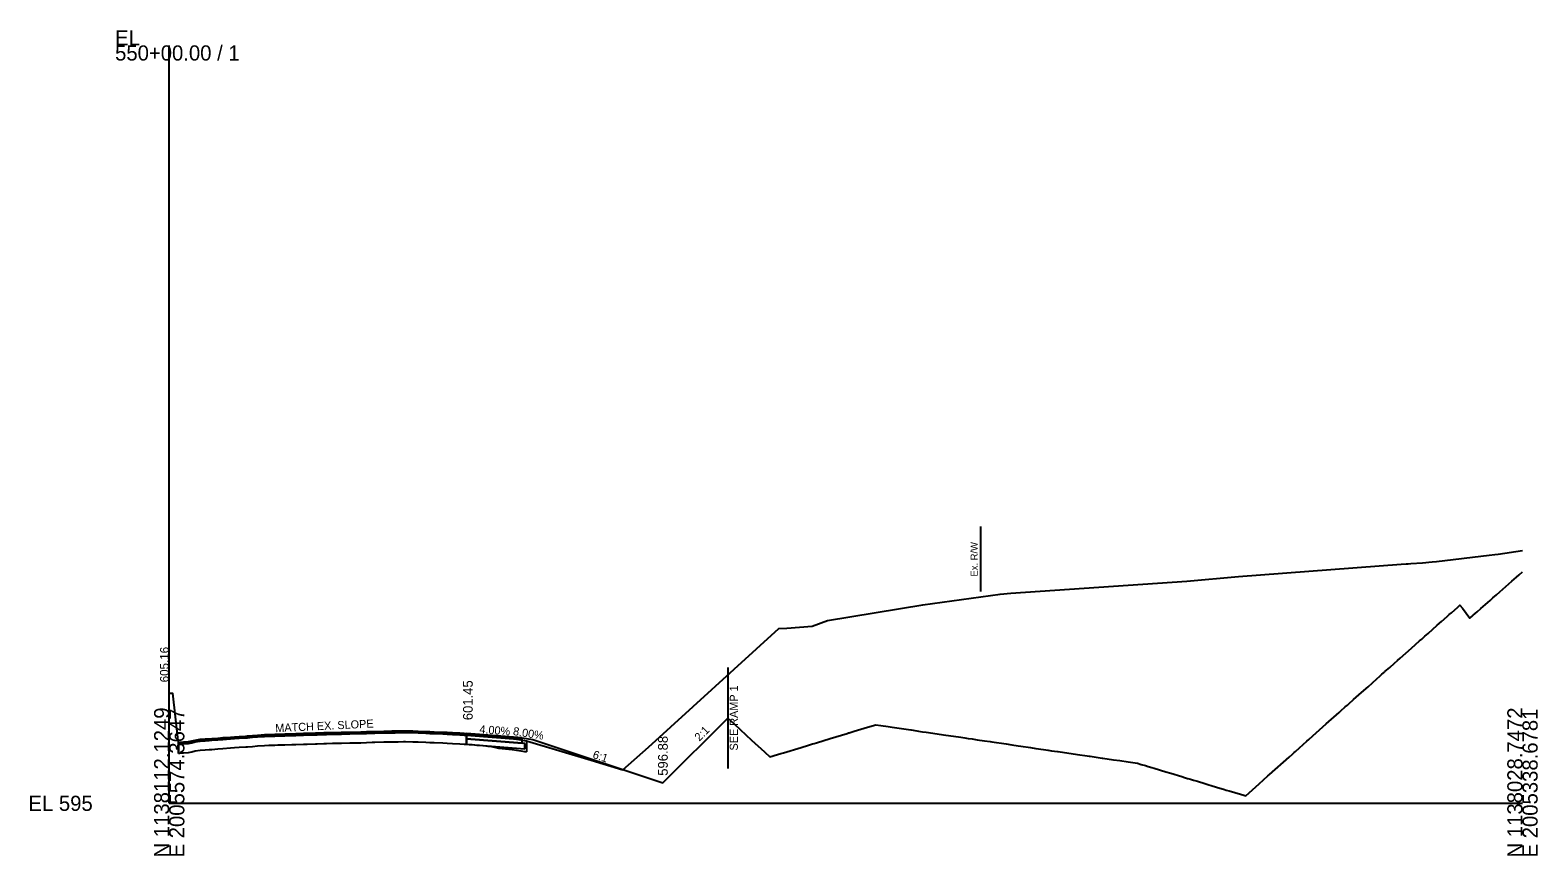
# Model space of a CAD drawing. Extents: x -201 to 2007062, y -213 to 1139737.
# Drawn here: x -25.7 to 252.8, y 5990.3 to 6142.7 of the extents above; entities that cross this region are included whole.
import ezdxf

# ---------------------------------------------------------------- set-up
doc = ezdxf.new("R2010")
doc.units = 0
for name, color, linetype in [('Default', 7, 'Continuous'), ('RD_DTM_Design_FG', 7, 'Continuous'), ('RD_GPK_XS_Cell', 7, 'Continuous'), ('RD_Sketch1', 7, 'Continuous'), ('RD_XS_Base', 7, 'Continuous'), ('RD_XS_EarthShd', 7, 'Continuous'), ('RD_XS_ExGround', 7, 'Continuous'), ('RD_XS_ExPaveRet', 7, 'Continuous'), ('RD_XS_ExRW', 7, 'Continuous'), ('RD_XS_PaveOvlay', 7, 'Continuous'), ('RD_XS_PaveShd', 7, 'Continuous'), ('RD_XS_SideStreet', 7, 'Continuous'), ('RD_XS_TieSlope', 7, 'Continuous'), ('RD_XS_TX_Ditch', 7, 'Continuous'), ('RD_XS_TX_Elev_EX', 7, 'Continuous'), ('RD_XS_TX_Elev_PR', 7, 'Continuous'), ('RD_XS_TX_Slope', 7, 'Continuous')]:
    doc.layers.add(name, color=color, linetype=linetype)

msp = doc.modelspace()

# ---------------------------------------------------------------- linework, layer by layer
at = {"layer": 'RD_DTM_Design_FG'}
msp.add_lwpolyline([(103.17, 6015.74), (104.42, 6014.59), (107.59, 6011.65), (109.95, 6009.48), (110.02, 6009.41), (110.94, 6008.56), (112.37, 6008.99), (112.99, 6009.18), (113.46, 6009.32), (116.74, 6010.32), (118.09, 6010.73), (118.84, 6010.96), (119.16, 6011.06), (119.6, 6011.19), (122.09, 6011.95), (125.26, 6012.91), (125.51, 6012.99), (125.59, 6013.01), (125.8, 6013.08), (126.51, 6013.29), (128.98, 6014.04), (130.52, 6014.51), (131.47, 6014.37), (132.83, 6014.17), (133.56, 6014.06), (136.99, 6013.55), (137.01, 6013.55), (137.08, 6013.54), (138.12, 6013.38), (138.41, 6013.34), (139.19, 6013.22), (139.86, 6013.12), (141.04, 6012.95), (141.45, 6012.89), (143.44, 6012.6), (143.97, 6012.52), (146.26, 6012.18), (147.01, 6012.07), (147.61, 6011.98), (148.31, 6011.88), (149.27, 6011.73), (150.64, 6011.53), (151.69, 6011.38), (151.99, 6011.33), (154.61, 6010.95), (155.67, 6010.79), (156.85, 6010.62), (157.32, 6010.55), (159.14, 6010.28), (160.12, 6010.14), (161.51, 6009.93), (161.97, 6009.86), (162.34, 6009.81), (162.37, 6009.8), (163.01, 6009.71), (164.11, 6009.55), (164.2, 6009.54), (167.82, 6009.01), (169.57, 6008.75), (169.92, 6008.7), (170.11, 6008.67), (171.26, 6008.5), (172.33, 6008.35), (172.5, 6008.32), (174.45, 6008.04), (175.63, 6007.87), (177.17, 6007.64), (178.87, 6007.39), (179.58, 6007.18), (180.35, 6006.95), (180.82, 6006.8), (181.54, 6006.59), (181.93, 6006.47), (184.14, 6005.81), (185.02, 6005.54), (187.06, 6004.93), (187.55, 6004.78), (188.14, 6004.6), (188.18, 6004.59), (188.68, 6004.44), (189.23, 6004.27), (189.95, 6004.06), (190.54, 6003.88), (190.74, 6003.82), (191.31, 6003.65), (192.07, 6003.42), (192.48, 6003.3), (193.49, 6002.99), (194.93, 6002.56), (195.29, 6002.45), (195.81, 6002.3), (197.89, 6001.68), (198.53, 6001.48), (198.89, 6001.38), (201.36, 6003.59), (202.97, 6005.04), (203.26, 6005.3), (206.87, 6008.52), (207.49, 6009.07), (207.76, 6009.31), (207.85, 6009.4), (208.04, 6009.57), (208.8, 6010.24), (210.18, 6011.47), (210.54, 6011.8), (211.27, 6012.45), (213.73, 6014.64), (214.7, 6015.5), (215.14, 6015.89), (216.14, 6016.79), (216.43, 6017.04), (217.27, 6017.8), (217.65, 6018.13), (217.91, 6018.36), (218.79, 6019.14), (220.26, 6020.45), (221.47, 6021.52), (223.09, 6022.96), (223.64, 6023.45), (224.04, 6023.81), (224.48, 6024.2), (224.6, 6024.3), (225.47, 6025.07), (226.33, 6025.84), (226.89, 6026.33), (227.39, 6026.77), (229.49, 6028.64), (230.99, 6029.96), (231.39, 6030.32), (231.95, 6030.82), (232.28, 6031.11), (232.55, 6031.35), (234.26, 6032.85), (235.06, 6033.56), (236.08, 6034.46), (236.48, 6034.82), (236.9, 6035.18), (238.03, 6036.18), (238.43, 6036.54), (238.9, 6036.01), (240.29, 6034.18), (240.34, 6034.22), (240.69, 6034.53), (240.9, 6034.72), (241.65, 6035.37), (242.3, 6035.94), (242.3, 6035.95), (244.01, 6037.45), (244.53, 6037.91), (245.19, 6038.49), (245.81, 6039.04), (246.36, 6039.52), (248.05, 6041.01), (248.92, 6041.76), (249.39, 6042.18), (250, 6042.72)], dxfattribs=at)
at = {"layer": 'RD_GPK_XS_Cell'}
for q in [(0, 6139.89), (250, 6000)]:
    msp.add_line((0, 6000), q, dxfattribs=at)
at = {"layer": 'RD_XS_Base'}
for points in [[(65.19, 6011.75), (54.94, 6012.56)], [(54.94, 6012.56), (54.94, 6011.9)], [(65.69, 6011.05), (65.19, 6011.09), (54.94, 6011.9)], [(54.94, 6011.9), (54.94, 6010.9)], [(54.94, 6011.9), (65.19, 6011.09)], [(54.94, 6010.9), (65.69, 6010.05)], [(65.19, 6011.09), (65.19, 6011.75)], [(65.69, 6010.05), (65.69, 6011.05)]]:
    msp.add_lwpolyline(points, dxfattribs=at)
at = {"layer": 'RD_XS_EarthShd'}
msp.add_lwpolyline([(65.19, 6012.08), (67.19, 6011.76)], dxfattribs=at)
at = {"layer": 'RD_XS_ExGround'}
msp.add_lwpolyline([(0, 6020.33), (0.63, 6020.35), (1.62, 6011.58), (1.7, 6011.21), (2.11, 6011.3), (2.64, 6011.32), (3.57, 6011.38), (4.18, 6011.51), (4.79, 6011.66), (5.69, 6011.81), (6.65, 6011.87), (7.4, 6011.91), (7.86, 6011.96), (8.95, 6012.05), (9.93, 6012.12), (11.35, 6012.23), (12.05, 6012.29), (12.92, 6012.36), (14.18, 6012.42), (14.49, 6012.45), (15.37, 6012.51), (16.3, 6012.58), (17.62, 6012.67), (18.42, 6012.71), (19.52, 6012.74), (20.09, 6012.77), (20.76, 6012.79), (21.36, 6012.81), (22.66, 6012.85), (23.37, 6012.87), (24.78, 6012.93), (25.46, 6012.94), (27.02, 6012.99), (27.36, 6013), (28.59, 6013.04), (29.03, 6013.05), (30.16, 6013.07), (31.49, 6013.09), (31.84, 6013.1), (33.36, 6013.16), (35.39, 6013.19), (36.43, 6013.24), (37.51, 6013.27), (37.99, 6013.28), (39.63, 6013.32), (41.13, 6013.35), (41.76, 6013.36), (42.3, 6013.37), (43.25, 6013.39), (43.66, 6013.4), (45, 6013.37), (46, 6013.33), (47.4, 6013.27), (48.12, 6013.24), (48.96, 6013.21), (50.53, 6013.14), (51.35, 6013.1), (52.36, 6013.05), (53.66, 6012.99), (54.48, 6012.94), (54.91, 6012.9), (55.42, 6012.88), (55.99, 6012.83), (56.8, 6012.75), (57.34, 6012.7), (58.52, 6012.59), (58.88, 6012.55), (59.51, 6012.47), (60.31, 6012.32), (60.85, 6012.19), (61.5, 6012.12), (63.34, 6011.94), (64.95, 6011.71), (65.61, 6011.59), (65.99, 6011.53), (77.92, 6007.96), (83.8, 6006.16), (88.52, 6010.34), (112.64, 6032.24), (114.11, 6032.35), (118.78, 6032.68), (121.59, 6033.71), (139.21, 6036.61), (153.51, 6038.57), (155.45, 6038.77), (188.01, 6040.99), (197.54, 6041.88), (227.56, 6044.12), (228.5, 6044.19), (228.91, 6044.22), (229.38, 6044.26), (231.5, 6044.41), (233.29, 6044.54), (234.12, 6044.6), (243.86, 6045.8), (244.92, 6045.93), (245.54, 6046), (250, 6046.63)], dxfattribs=at)
at = {"layer": 'RD_XS_ExPaveRet'}
for p, q in [((1.7, 6009.22), (1.7, 6011.22)), ((1.7, 6010.88), (1.7, 6009.22)), ((18.42, 6010.71), (19.52, 6010.74)), ((18.42, 6010.71), (19.52, 6010.74)), ((19.52, 6010.74), (20.09, 6010.77)), ((19.52, 6010.74), (20.09, 6010.77)), ((20.09, 6010.77), (20.76, 6010.79)), ((20.09, 6010.77), (20.76, 6010.79)), ((20.76, 6010.79), (21.36, 6010.81)), ((20.76, 6010.79), (21.36, 6010.81)), ((21.36, 6010.81), (22.66, 6010.85)), ((21.36, 6010.81), (22.66, 6010.85)), ((22.66, 6010.85), (23.37, 6010.87)), ((22.66, 6010.85), (23.37, 6010.87)), ((23.37, 6010.87), (24.78, 6010.93)), ((23.37, 6010.87), (24.78, 6010.93)), ((24.78, 6010.93), (25.46, 6010.94)), ((24.78, 6010.93), (25.46, 6010.94)), ((25.46, 6010.94), (27.02, 6010.99)), ((25.46, 6010.94), (27.02, 6010.99)), ((27.02, 6010.99), (27.36, 6011)), ((27.02, 6010.99), (27.36, 6011)), ((27.36, 6011), (28.59, 6011.04)), ((27.36, 6011), (28.59, 6011.04)), ((28.59, 6011.04), (29.03, 6011.05)), ((28.59, 6011.04), (29.03, 6011.05)), ((29.03, 6011.05), (30.16, 6011.07)), ((29.03, 6011.05), (30.16, 6011.07)), ((30.16, 6011.07), (31.49, 6011.09)), ((30.16, 6011.07), (31.49, 6011.09)), ((31.49, 6011.09), (31.84, 6011.1)), ((31.49, 6011.09), (31.84, 6011.1)), ((31.84, 6011.1), (33.36, 6011.16)), ((31.84, 6011.1), (33.36, 6011.16)), ((33.36, 6011.16), (35.39, 6011.19)), ((33.36, 6011.16), (35.39, 6011.19)), ((35.39, 6011.19), (36.43, 6011.24)), ((35.39, 6011.19), (36.43, 6011.24)), ((36.43, 6011.24), (37.51, 6011.27)), ((36.43, 6011.24), (37.51, 6011.27)), ((37.51, 6011.27), (37.99, 6011.28)), ((37.51, 6011.27), (37.99, 6011.28)), ((37.99, 6011.28), (39.63, 6011.32)), ((37.99, 6011.28), (39.63, 6011.32)), ((39.63, 6011.32), (41.13, 6011.35)), ((39.63, 6011.32), (41.13, 6011.35)), ((41.13, 6011.35), (41.76, 6011.36)), ((41.13, 6011.35), (41.76, 6011.36)), ((41.76, 6011.36), (42.3, 6011.37)), ((41.76, 6011.36), (42.3, 6011.37)), ((42.3, 6011.37), (43.25, 6011.39)), ((42.3, 6011.37), (43.25, 6011.39)), ((43.25, 6011.39), (43.66, 6011.4)), ((43.25, 6011.39), (43.66, 6011.4)), ((43.66, 6011.4), (45, 6011.37)), ((43.66, 6011.4), (45, 6011.37)), ((45, 6011.37), (46, 6011.33)), ((45, 6011.37), (46, 6011.33)), ((46, 6011.33), (47.4, 6011.27)), ((46, 6011.33), (47.4, 6011.27)), ((47.4, 6011.27), (48.12, 6011.24)), ((47.4, 6011.27), (48.12, 6011.24)), ((48.12, 6011.24), (48.96, 6011.21)), ((48.12, 6011.24), (48.96, 6011.21)), ((48.96, 6011.21), (50.53, 6011.14)), ((48.96, 6011.21), (50.53, 6011.14)), ((50.53, 6011.14), (51.35, 6011.1)), ((50.53, 6011.14), (51.35, 6011.1)), ((51.35, 6011.1), (52.36, 6011.05)), ((51.35, 6011.1), (52.36, 6011.05)), ((52.36, 6011.05), (53.66, 6010.99)), ((52.36, 6011.05), (53.66, 6010.99)), ((53.66, 6010.99), (54.48, 6010.94)), ((53.66, 6010.99), (54.48, 6010.94)), ((54.48, 6010.94), (54.91, 6010.9)), ((54.48, 6010.94), (54.91, 6010.9)), ((54.91, 6010.9), (55.42, 6010.88)), ((54.91, 6010.9), (54.94, 6010.9)), ((54.94, 6012.56), (54.94, 6012.57)), ((54.94, 6011.9), (54.94, 6012.56)), ((54.94, 6010.9), (54.94, 6011.9)), ((54.94, 6010.9), (54.94, 6010.9)), ((54.94, 6010.9), (54.94, 6010.9)), ((55.42, 6010.88), (55.99, 6010.83)), ((55.99, 6010.83), (56.8, 6010.75)), ((56.8, 6010.75), (57.34, 6010.7)), ((65.99, 6011.53), (65.99, 6009.53)), ((1.7, 6009.21), (2.11, 6009.3)), ((1.7, 6009.21), (2.11, 6009.3)), ((1.7, 6009.22), (1.7, 6009.21)), ((1.7, 6009.22), (1.7, 6009.21)), ((2.11, 6009.3), (2.64, 6009.32)), ((2.11, 6009.3), (2.64, 6009.32)), ((2.64, 6009.32), (3.57, 6009.38)), ((2.64, 6009.32), (3.57, 6009.38)), ((3.57, 6009.38), (4.18, 6009.51)), ((3.57, 6009.38), (4.18, 6009.51)), ((4.18, 6009.51), (4.79, 6009.66)), ((4.18, 6009.51), (4.79, 6009.66)), ((4.79, 6009.66), (5.69, 6009.81)), ((4.79, 6009.66), (5.69, 6009.81)), ((5.69, 6009.81), (6.65, 6009.87)), ((5.69, 6009.81), (6.65, 6009.87)), ((6.65, 6009.87), (7.4, 6009.91)), ((6.65, 6009.87), (7.4, 6009.91)), ((7.4, 6009.91), (7.86, 6009.96)), ((7.4, 6009.91), (7.86, 6009.96)), ((7.86, 6009.96), (8.95, 6010.05)), ((7.86, 6009.96), (8.95, 6010.05)), ((8.95, 6010.05), (9.93, 6010.12)), ((8.95, 6010.05), (9.93, 6010.12)), ((9.93, 6010.12), (11.35, 6010.23)), ((9.93, 6010.12), (11.35, 6010.23)), ((11.35, 6010.23), (12.05, 6010.29)), ((11.35, 6010.23), (12.05, 6010.29)), ((12.05, 6010.29), (12.92, 6010.36)), ((12.05, 6010.29), (12.92, 6010.36)), ((12.92, 6010.36), (14.18, 6010.42)), ((12.92, 6010.36), (14.18, 6010.42)), ((14.18, 6010.42), (14.49, 6010.45)), ((14.18, 6010.42), (14.49, 6010.45)), ((14.49, 6010.45), (15.37, 6010.51)), ((14.49, 6010.45), (15.37, 6010.51)), ((15.37, 6010.51), (16.3, 6010.58)), ((15.37, 6010.51), (16.3, 6010.58)), ((16.3, 6010.58), (17.62, 6010.67)), ((16.3, 6010.58), (17.62, 6010.67)), ((17.62, 6010.67), (18.42, 6010.71)), ((17.62, 6010.67), (18.42, 6010.71)), ((57.34, 6010.7), (58.52, 6010.59)), ((58.52, 6010.59), (58.88, 6010.55)), ((58.88, 6010.55), (59.51, 6010.47)), ((59.51, 6010.47), (60.31, 6010.32)), ((60.31, 6010.32), (60.85, 6010.19)), ((60.85, 6010.19), (61.5, 6010.12)), ((61.5, 6010.12), (63.34, 6009.94)), ((63.34, 6009.94), (64.95, 6009.71)), ((64.95, 6009.71), (65.61, 6009.59)), ((65.61, 6009.59), (65.99, 6009.53)), ((65.99, 6009.53), (65.99, 6009.53))]:
    msp.add_line(p, q, dxfattribs=at)
for points in [[(54.94, 6012.57), (54.91, 6012.57), (54.48, 6012.6), (53.66, 6012.66), (52.36, 6012.71), (51.35, 6012.77), (50.53, 6012.81), (48.96, 6012.87), (48.12, 6012.91), (47.4, 6012.94), (46, 6013), (45, 6013.04), (43.66, 6013.07), (43.25, 6013.06), (42.3, 6013.04), (41.76, 6013.03), (41.13, 6013.02), (39.63, 6012.99), (37.99, 6012.95), (37.51, 6012.94), (36.43, 6012.91), (35.39, 6012.86), (33.36, 6012.83), (31.84, 6012.77), (31.49, 6012.76), (30.16, 6012.74), (29.03, 6012.72), (28.59, 6012.7), (27.36, 6012.66), (27.02, 6012.65), (25.46, 6012.61), (24.78, 6012.6), (23.37, 6012.54), (22.66, 6012.52), (21.36, 6012.48), (20.76, 6012.46), (20.09, 6012.43), (19.52, 6012.41), (18.42, 6012.38), (17.62, 6012.33), (16.3, 6012.25), (15.37, 6012.18), (14.49, 6012.11), (14.18, 6012.09), (12.92, 6012.02), (12.05, 6011.96), (11.35, 6011.9), (9.93, 6011.79), (8.95, 6011.72), (7.86, 6011.63), (7.4, 6011.58), (6.65, 6011.54), (5.69, 6011.47), (4.79, 6011.33), (4.18, 6011.18), (3.57, 6011.05), (2.64, 6010.99), (2.11, 6010.97), (1.7, 6010.88)], [(1.7, 6010.88), (1.7, 6010.88)]]:
    msp.add_lwpolyline(points, dxfattribs=at)
at = {"layer": 'RD_XS_ExRW'}
msp.add_line((149.85, 6051.09), (149.85, 6039.09), dxfattribs=at)
at = {"layer": 'RD_XS_PaveOvlay'}
for points in [[(1.7, 6011.22), (1.7, 6011.21), (2.11, 6011.3), (2.64, 6011.32), (3.57, 6011.38), (4.18, 6011.51), (4.79, 6011.66), (5.69, 6011.81), (6.65, 6011.87), (7.4, 6011.91), (7.86, 6011.96), (8.95, 6012.05), (9.93, 6012.12), (11.35, 6012.23), (12.05, 6012.29), (12.92, 6012.36), (14.18, 6012.42), (14.49, 6012.45), (15.37, 6012.51), (16.3, 6012.58), (17.62, 6012.67), (18.42, 6012.71), (19.52, 6012.74), (20.09, 6012.77), (20.76, 6012.79), (21.36, 6012.81), (22.66, 6012.85), (23.37, 6012.87), (24.78, 6012.93), (25.46, 6012.94), (27.02, 6012.99), (27.36, 6013), (28.59, 6013.04), (29.03, 6013.05), (30.16, 6013.07), (31.49, 6013.09), (31.84, 6013.1), (33.36, 6013.16), (35.39, 6013.19), (36.43, 6013.24), (37.51, 6013.27), (37.99, 6013.28), (39.63, 6013.32), (41.13, 6013.35), (41.76, 6013.36), (42.3, 6013.37), (43.25, 6013.39), (43.66, 6013.4), (45, 6013.37), (46, 6013.33), (47.4, 6013.27), (48.12, 6013.24), (48.96, 6013.21), (50.53, 6013.14), (51.35, 6013.1), (52.36, 6013.05), (53.66, 6012.99), (54.48, 6012.94), (54.91, 6012.9), (54.94, 6012.9)], [(1.7, 6010.88), (1.7, 6010.88), (2.11, 6010.97), (2.64, 6010.99), (3.57, 6011.05), (4.18, 6011.18), (4.79, 6011.33), (5.69, 6011.47), (6.65, 6011.54), (7.4, 6011.58), (7.86, 6011.63), (8.95, 6011.72), (9.93, 6011.79), (11.35, 6011.9), (12.05, 6011.96), (12.92, 6012.02), (14.18, 6012.09), (14.49, 6012.11), (15.37, 6012.18), (16.3, 6012.25), (17.62, 6012.33), (18.42, 6012.38), (19.52, 6012.41), (20.09, 6012.43), (20.76, 6012.46), (21.36, 6012.48), (22.66, 6012.52), (23.37, 6012.54), (24.78, 6012.6), (25.46, 6012.61), (27.02, 6012.65), (27.36, 6012.66), (28.59, 6012.7), (29.03, 6012.72), (30.16, 6012.74), (31.49, 6012.76), (31.84, 6012.77), (33.36, 6012.83), (35.39, 6012.86), (36.43, 6012.91), (37.51, 6012.94), (37.99, 6012.95), (39.63, 6012.99), (41.13, 6013.02), (41.76, 6013.03), (42.3, 6013.04), (43.25, 6013.06), (43.66, 6013.07), (45, 6013.04), (46, 6013), (47.4, 6012.94), (48.12, 6012.91), (48.96, 6012.87), (50.53, 6012.81), (51.35, 6012.77), (52.36, 6012.71), (53.66, 6012.66), (54.48, 6012.6), (54.91, 6012.57), (54.94, 6012.57)]]:
    msp.add_lwpolyline(points, dxfattribs=at)
at = {"layer": 'RD_XS_PaveShd'}
for points in [[(65.19, 6012.08), (54.94, 6012.9)], [(54.94, 6012.9), (54.94, 6012.56)], [(54.94, 6012.56), (65.19, 6011.75)], [(65.19, 6011.75), (65.19, 6012.08)]]:
    msp.add_lwpolyline(points, dxfattribs=at)
at = {"layer": 'RD_XS_SideStreet'}
msp.add_line((103.17, 6025.08), (103.17, 6006.4), dxfattribs=at)
at = {"layer": 'RD_XS_TieSlope'}
msp.add_lwpolyline([(67.19, 6011.76), (91.2, 6003.77), (103.17, 6015.74)], dxfattribs=at)

# ---------------------------------------------------------------- texts
at = {"layer": 'Default'}
msp.add_text('-', height=0.0001, dxfattribs=at).set_placement((0, 6000))
at = {"layer": 'RD_GPK_XS_Cell'}
for s, p in [('EL', (-10, 6139.89)), ('550+00.00 / 1', (-10, 6137.09)), ('EL 595', (-26, 5998.6))]:
    msp.add_text(s, height=2.8, dxfattribs=at).set_placement(p)
for s, p in [('N 1138112.1249', (0, 5990)), ('E 2005574.3647', (2.8, 5990)), ('N 1138028.7472', (250, 5990)), ('E 2005338.6781', (252.8, 5990))]:
    msp.add_text(s, height=2.8, rotation=90, dxfattribs=at).set_placement(p)
at = {"layer": 'RD_Sketch1'}
for s, p in [('Exterior Boundary', (120.38, 6033.45)), ('LOC_C_R', (120.61, 6033.45)), ('Exterior Boundary', (54.38, 6012.85)), ('EP_X_R', (54.68, 6012.85)), ('EP_X2', (54.73, 6011.85)), ('EP_X3', (54.73, 6010.85)), ('EP_X1', (54.74, 6012.51)), ('550+00.00', (60.14, 6012.41)), ('ESP1_R', (64.93, 6011.7)), ('ESP2_R', (64.93, 6011.04)), ('ESP_R', (64.96, 6012.03)), ('ESP4_R', (65.43, 6011)), ('ES_R', (67.01, 6011.71)), ('ESP3_R', (65.43, 6010)), ('549+99.80', (81.81, 6006.74)), ('Cut_Ditch_R', (90.81, 6003.72))]:
    msp.add_text(s, height=0.05, dxfattribs=at).set_placement(p)
at = {"layer": 'RD_XS_ExRW'}
msp.add_text('Ex. R/W ', height=1.3, rotation=90, dxfattribs=at).set_placement((149.35, 6041.85))
at = {"layer": 'RD_XS_SideStreet'}
msp.add_text('SEE RAMP 1', height=1.5, rotation=90, dxfattribs=at).set_placement((105.05, 6009.74))
at = {"layer": 'RD_XS_TX_Ditch'}
msp.add_text('596.88', height=1.8, rotation=90, dxfattribs=at).set_placement((92.1, 6005.08))
at = {"layer": 'RD_XS_TX_Elev_EX'}
msp.add_text('605.16', height=1.6, rotation=90, dxfattribs=at).set_placement((-0.1, 6022.33))
at = {"layer": 'RD_XS_TX_Elev_PR'}
msp.add_text('601.45', height=1.8, rotation=90, dxfattribs=at).set_placement((56.07, 6015.34))
at = {"layer": 'RD_XS_TX_Slope'}
for s, rotation, p in [('MATCH EX. SLOPE', 2.7318, (19.63, 6013.12)), ('4.00%', 355.4406, (57.26, 6012.96)), ('8.00%', 350.9255, (63.44, 6012.62)), ('2:1', 44.9986, (97.94, 6011.38)), ('6:1', 341.5834, (78.11, 6008.39))]:
    msp.add_text(s, height=1.5, rotation=rotation, dxfattribs=at).set_placement(p)

doc.saveas('drawing.dxf')
